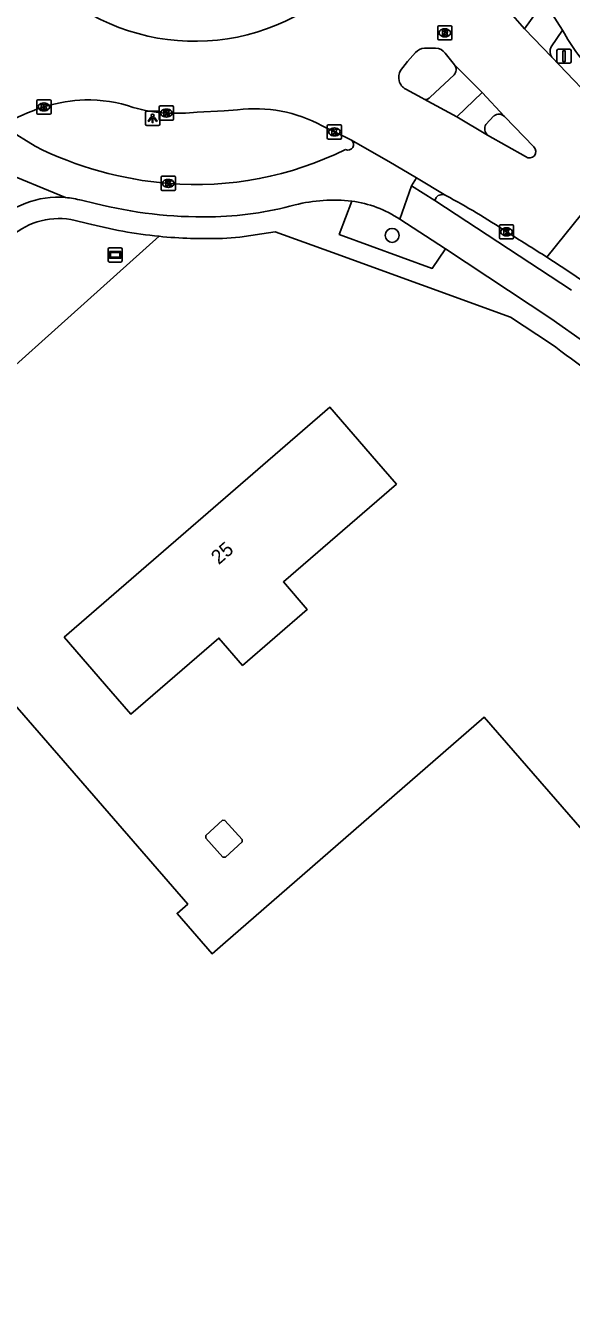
# Model space of a CAD drawing. Extents: x 156141 to 158132, y 385651 to 388399.
# Drawn here: x 156663.7 to 156702, y 386916.4 to 387006.5 of the extents above; entities that cross this region are included whole.
import ezdxf

# ---------------------------------------------------------------- set-up
doc = ezdxf.new("R2010")
doc.units = 0
for name, color, linetype in [('IMGEO_Boom', 7, 'Continuous'), ('IMGEO_Fietspad_gesloten', 7, 'Continuous'), ('IMGEO_Groenvoorziening', 7, 'Continuous'), ('IMGEO_Hek', 7, 'Continuous'), ('IMGEO_Kolk', 7, 'Continuous'), ('IMGEO_Lage_trafo', 7, 'Continuous'), ('IMGEO_Lichtpunt', 7, 'Continuous'), ('IMGEO_Pand', 7, 'Continuous'), ('IMGEO_Pand_nummerreeks', 7, 'Continuous'), ('IMGEO_Rijbaan_lokaal_gesloten', 7, 'Continuous'), ('IMGEO_Rioolput', 7, 'Continuous'), ('IMGEO_Verkeersbordpaal', 7, 'Continuous'), ('IMGEO_Verklikker', 7, 'Continuous'), ('IMGEO_Voetpad_gesloten', 7, 'Continuous'), ('IMGEO_Voetpad_open', 7, 'Continuous')]:
    doc.layers.add(name, color=color, linetype=linetype)

msp = doc.modelspace()

# ---------------------------------------------------------------- linework, layer by layer
at = {"layer": 'IMGEO_Boom'}
msp.add_circle((156689.433, 386991.752), 0.489, dxfattribs=at)
at = {"layer": 'IMGEO_Fietspad_gesloten'}
for points in [[(156698.711, 387006.225), (156700.096, 387008.143), (156701.387, 387006.132)], [(156693.775, 387002.996), (156692.105, 387001.447)], [(156695.751, 387001.772), (156693.974, 387000.053)], [(156664.391, 386998), (156662.509, 386999.178)], [(156661.84, 386996.318), (156666.533, 386994.404)], [(156689.966, 386992.892), (156690.795, 386995.224)], [(156691.132, 386995.796), (156690.795, 386995.224)], [(156690.795, 386995.224), (156692.417, 386994.202)], [(156668.614, 386993.983), (156667.65, 386994.209)], [(156702.016, 386987.906), (156692.417, 386994.202)], [(156689.966, 386992.892), (156693.165, 386990.801)], [(156703.023, 386984.189), (156700.556, 386985.925), (156693.165, 386990.801)]]:
    msp.add_lwpolyline(points, dxfattribs=at)
for centre, radius, start, end in [((156713.634, 387012.787), 13.938, 208.5177, 224.98093), ((156693.328, 387003.377), 0.587, 319.52372, 34.19696), ((156691.781, 387001.685), 0.402, 256.11781, 323.67305), ((156675.767, 387020.752), 25.438, 243.4358, 265.41669), ((156686.341, 386998.114), 0.383, 241.1208, 58.64655), ((156675.698, 387018.728), 23.415, 265.18946, 296.52958), ((156665.996, 386988.061), 6.366, 85.16238, 136.3351), ((156666.026, 386988.205), 6.22, 74.86733, 85.32747), ((156676.28, 387024.756), 31.713, 256.01146, 270.71731), ((156676.29, 387017.188), 24.146, 270.9173, 285.22162), ((156685.357, 386983.114), 11.114, 83.58227, 104.20108), ((156685.487, 386986.096), 8.139, 56.6108, 82.14663)]:
    msp.add_arc(centre, radius, start, end, dxfattribs=at)
at = {"layer": 'IMGEO_Groenvoorziening'}
msp.add_lwpolyline([(156673.084, 386991.685), (156655.481, 386975.893)], dxfattribs=at)
at = {"layer": 'IMGEO_Hek'}
msp.add_lwpolyline([(156655.481, 386975.893), (156673.084, 386991.685)], dxfattribs=at)
at = {"layer": 'IMGEO_Kolk'}
for p, q in [((156664.51, 387000.33), (156664.51, 387001.182)), ((156664.585, 387001.256), (156665.437, 387001.256)), ((156664.998, 387001.036), (156665.023, 387001.036)), ((156665.511, 387001.182), (156665.511, 387000.33)), ((156673.101, 386999.898), (156673.101, 387000.75)), ((156673.176, 387000.824), (156674.028, 387000.824)), ((156673.589, 387000.604), (156673.614, 387000.604)), ((156674.102, 387000.75), (156674.102, 386999.898)), ((156665.437, 387000.256), (156664.585, 387000.256)), ((156665.021, 387000.476), (156664.996, 387000.476)), ((156674.028, 386999.824), (156673.176, 386999.824)), ((156673.612, 387000.044), (156673.587, 387000.044)), ((156684.886, 386998.58), (156684.886, 386999.432)), ((156684.961, 386999.506), (156685.813, 386999.506)), ((156685.374, 386999.286), (156685.399, 386999.286)), ((156685.887, 386999.432), (156685.887, 386998.58)), ((156685.813, 386998.506), (156684.961, 386998.506)), ((156685.397, 386998.726), (156685.372, 386998.726)), ((156673.233, 386994.971), (156673.233, 386995.823)), ((156673.308, 386995.897), (156674.16, 386995.897)), ((156673.721, 386995.677), (156673.746, 386995.677)), ((156674.234, 386995.823), (156674.234, 386994.971)), ((156674.16, 386994.897), (156673.308, 386994.897)), ((156673.744, 386995.117), (156673.719, 386995.117)), ((156697.026, 386992.5), (156697.878, 386992.5)), ((156696.951, 386991.574), (156696.951, 386992.426)), ((156697.462, 386991.72), (156697.437, 386991.72)), ((156697.439, 386992.28), (156697.464, 386992.28)), ((156697.952, 386992.426), (156697.952, 386991.574)), ((156697.878, 386991.5), (156697.026, 386991.5))]:
    msp.add_line(p, q, dxfattribs=at)
for points in [[(156664.51, 387000.33), (156664.51, 387001.182)], [(156664.585, 387001.256), (156665.437, 387001.256)], [(156664.831, 387000.956), (156664.954, 387000.956), (156664.954, 387000.805), (156665.084, 387000.956), (156665.248, 387000.956), (156665.102, 387000.805), (156665.255, 387000.556), (156665.103, 387000.556), (156665.018, 387000.72), (156664.954, 387000.653), (156664.954, 387000.556), (156664.831, 387000.556), (156664.831, 387000.956)], [(156665.511, 387001.182), (156665.511, 387000.33)], [(156673.101, 386999.898), (156673.101, 387000.75)], [(156673.176, 387000.824), (156674.028, 387000.824)], [(156674.102, 387000.75), (156674.102, 386999.898)], [(156665.437, 387000.256), (156664.585, 387000.256)], [(156674.028, 386999.824), (156673.176, 386999.824)], [(156673.422, 387000.524), (156673.545, 387000.524), (156673.545, 387000.373), (156673.675, 387000.524), (156673.839, 387000.524), (156673.693, 387000.373), (156673.846, 387000.124), (156673.694, 387000.124), (156673.609, 387000.288), (156673.545, 387000.221), (156673.545, 387000.124), (156673.422, 387000.124), (156673.422, 387000.524)], [(156684.886, 386998.58), (156684.886, 386999.432)], [(156684.961, 386999.506), (156685.813, 386999.506)], [(156685.207, 386999.206), (156685.33, 386999.206), (156685.33, 386999.055), (156685.46, 386999.206), (156685.624, 386999.206), (156685.478, 386999.055), (156685.631, 386998.806), (156685.479, 386998.806), (156685.394, 386998.97), (156685.33, 386998.903), (156685.33, 386998.806), (156685.207, 386998.806), (156685.207, 386999.206)], [(156685.887, 386999.432), (156685.887, 386998.58)], [(156685.813, 386998.506), (156684.961, 386998.506)], [(156673.233, 386994.971), (156673.233, 386995.823)], [(156673.308, 386995.897), (156674.16, 386995.897)], [(156673.554, 386995.597), (156673.677, 386995.597), (156673.677, 386995.446), (156673.807, 386995.597), (156673.971, 386995.597), (156673.825, 386995.446), (156673.978, 386995.197), (156673.826, 386995.197), (156673.741, 386995.361), (156673.677, 386995.294), (156673.677, 386995.197), (156673.554, 386995.197), (156673.554, 386995.597)], [(156674.234, 386995.823), (156674.234, 386994.971)], [(156674.16, 386994.897), (156673.308, 386994.897)], [(156697.026, 386992.5), (156697.878, 386992.5)], [(156696.951, 386991.574), (156696.951, 386992.426)], [(156697.272, 386992.2), (156697.395, 386992.2), (156697.395, 386992.049), (156697.525, 386992.2), (156697.689, 386992.2), (156697.543, 386992.049), (156697.696, 386991.8), (156697.544, 386991.8), (156697.459, 386991.964), (156697.395, 386991.897), (156697.395, 386991.8), (156697.272, 386991.8), (156697.272, 386992.2)], [(156697.952, 386992.426), (156697.952, 386991.574)], [(156697.878, 386991.5), (156697.026, 386991.5)]]:
    msp.add_lwpolyline(points, dxfattribs=at)
for centre, start, end in [((156664.587, 387001.18), 91.55205, 178.44795), ((156664.587, 387001.18), 91.55205, 178.44795), ((156665.435, 387001.18), 1.55205, 88.44795), ((156665.435, 387001.18), 1.55205, 88.44795), ((156673.178, 387000.748), 91.55205, 178.44795), ((156673.178, 387000.748), 91.55205, 178.44795), ((156674.026, 387000.748), 1.55205, 88.44795), ((156674.026, 387000.748), 1.55205, 88.44795), ((156664.587, 387000.332), 181.55205, 268.44795), ((156664.587, 387000.332), 181.55205, 268.44795), ((156665.435, 387000.332), 271.55205, 358.44795), ((156665.435, 387000.332), 271.55205, 358.44795), ((156673.178, 386999.9), 181.55205, 268.44795), ((156673.178, 386999.9), 181.55205, 268.44795), ((156674.026, 386999.9), 271.55205, 358.44795), ((156674.026, 386999.9), 271.55205, 358.44795), ((156684.963, 386999.43), 91.55205, 178.44795), ((156684.963, 386999.43), 91.55205, 178.44795), ((156685.811, 386999.43), 1.55205, 88.44795), ((156685.811, 386999.43), 1.55205, 88.44795), ((156684.963, 386998.582), 181.55205, 268.44795), ((156684.963, 386998.582), 181.55205, 268.44795), ((156685.811, 386998.582), 271.55205, 358.44795), ((156685.811, 386998.582), 271.55205, 358.44795), ((156673.31, 386995.821), 91.55205, 178.44795), ((156673.31, 386995.821), 91.55205, 178.44795), ((156674.158, 386995.821), 1.55205, 88.44795), ((156674.158, 386995.821), 1.55205, 88.44795), ((156673.31, 386994.973), 181.55205, 268.44795), ((156673.31, 386994.973), 181.55205, 268.44795), ((156674.158, 386994.973), 271.55205, 358.44795), ((156674.158, 386994.973), 271.55205, 358.44795), ((156697.028, 386992.424), 91.55205, 178.44795), ((156697.028, 386992.424), 91.55205, 178.44795), ((156697.876, 386992.424), 1.55205, 88.44795), ((156697.876, 386992.424), 1.55205, 88.44795), ((156697.028, 386991.576), 181.55205, 268.44795), ((156697.028, 386991.576), 181.55205, 268.44795), ((156697.876, 386991.576), 271.55205, 358.44795), ((156697.876, 386991.576), 271.55205, 358.44795)]:
    msp.add_arc(centre, 0.0765, start, end, dxfattribs=at)
for centre, major_axis, ratio, start_param, end_param in [((156664.997, 387000.756), (-0.387, 0.002), 0.722429, 4.712389, 7.853982), ((156665.022, 387000.756), (-0.39, 0.002), 0.717154, 1.570796, 4.712389), ((156673.588, 387000.324), (-0.387, 0.002), 0.722429, 4.712389, 7.853982), ((156673.613, 387000.324), (-0.39, 0.002), 0.717154, 1.570796, 4.712389), ((156685.373, 386999.006), (-0.387, 0.002), 0.722429, 4.712389, 7.853982), ((156685.398, 386999.006), (-0.39, 0.002), 0.717154, 1.570796, 4.712389), ((156673.72, 386995.397), (-0.387, 0.002), 0.722429, 4.712389, 7.853982), ((156673.745, 386995.397), (-0.39, 0.002), 0.717154, 1.570796, 4.712389), ((156697.438, 386992), (-0.387, 0.002), 0.722429, 4.712389, 7.853982), ((156697.463, 386992), (-0.39, 0.002), 0.717154, 1.570796, 4.712389)]:
    msp.add_ellipse(centre, major_axis=major_axis, ratio=ratio, start_param=start_param, end_param=end_param, dxfattribs=at)
at = {"layer": 'IMGEO_Lage_trafo'}
msp.add_lwpolyline([(156676.361, 386949.497), (156676.371, 386949.672), (156677.539, 386950.742), (156677.709, 386950.734), (156678.912, 386949.403), (156678.921, 386949.226), (156677.749, 386948.16), (156677.562, 386948.171), (156676.361, 386949.497)], dxfattribs=at)
at = {"layer": 'IMGEO_Lichtpunt'}
for p, q in [((156672.139, 387000.363), (156672.139, 386999.556)), ((156672.139, 387000.363), (156672.139, 386999.556)), ((156673.041, 387000.458), (156672.233, 387000.458)), ((156673.041, 387000.458), (156672.233, 387000.458)), ((156673.135, 386999.556), (156673.135, 387000.363)), ((156673.135, 386999.556), (156673.135, 387000.363)), ((156672.233, 386999.462), (156673.041, 386999.462)), ((156672.233, 386999.462), (156673.041, 386999.462))]:
    msp.add_line(p, q, dxfattribs=at)
for points in [[(156672.513, 387000.027), (156672.552, 386999.999), (156672.364, 386999.737), (156672.326, 386999.764), (156672.513, 387000.027)], [(156672.615, 386999.979), (156672.662, 386999.979), (156672.662, 386999.657), (156672.615, 386999.657), (156672.615, 386999.979)], [(156672.725, 386999.999), (156672.763, 387000.026), (156672.95, 386999.764), (156672.911, 386999.736), (156672.725, 386999.999)]]:
    msp.add_lwpolyline(points, dxfattribs=at)
msp.add_circle((156672.638, 387000.161), 0.0994, dxfattribs=at)
for centre, start, end in [((156672.233, 387000.363), 90, 180), ((156672.233, 387000.363), 90, 180), ((156673.041, 387000.363), 0, 90), ((156673.041, 387000.363), 0, 90), ((156672.233, 386999.556), 180, 270), ((156672.233, 386999.556), 180, 270), ((156673.041, 386999.556), 270, 0), ((156673.041, 386999.556), 270, 360)]:
    msp.add_arc(centre, 0.0946, start, end, dxfattribs=at)
at = {"layer": 'IMGEO_Pand'}
for points in [[(156666.435, 386963.585), (156685.066, 386979.707), (156688.338, 386975.926), (156689.732, 386974.316), (156681.806, 386967.458), (156683.477, 386965.527), (156678.942, 386961.603), (156677.285, 386963.518), (156671.114, 386958.178), (156669.706, 386959.805), (156666.435, 386963.585)], [(156632.813, 386922.979), (156634.616, 386924.548), (156624.471, 386936.156), (156653.216, 386961.202), (156653.899, 386960.418), (156657.074, 386963.181), (156656.396, 386963.957), (156657.592, 386965.002), (156675.1, 386944.876), (156674.346, 386944.22), (156676.807, 386941.391), (156677.562, 386942.047), (156695.881, 386957.981), (156709.331, 386942.518), (156708.055, 386941.409), (156711.049, 386937.974), (156712.323, 386939.084), (156722.503, 386927.388), (156699.852, 386907.726), (156709.71, 386896.409), (156679.137, 386869.744), (156632.813, 386922.979)]]:
    msp.add_lwpolyline(points, dxfattribs=at)
at = {"layer": 'IMGEO_Rijbaan_lokaal_gesloten'}
for points in [[(156697.053, 387008.162), (156697.416, 387007.737), (156698.711, 387006.225)], [(156700.643, 387004.256), (156698.711, 387006.225)], [(156690.024, 387003.314), (156690.513, 387003.945), (156691.076, 387004.581)], [(156691.699, 387004.871), (156692.479, 387004.875)], [(156693.153, 387004.516), (156693.814, 387003.707)], [(156706.491, 386997.928), (156704.25, 387000.459), (156700.643, 387004.256)], [(156693.814, 387003.707), (156695.751, 387001.772)], [(156691.685, 387001.295), (156691.506, 387001.392), (156690.387, 387002.002)], [(156695.751, 387001.772), (156697.301, 387000.092)], [(156675.762, 387000.384), (156677.652, 387000.475), (156678.6, 387000.563)], [(156693.974, 387000.053), (156691.685, 387001.295)], [(156696.126, 386998.785), (156693.974, 387000.053)], [(156697.301, 387000.092), (156699.359, 386997.959)], [(156684.526, 386999.439), (156685.387, 386999.006), (156686.54, 386998.441)], [(156698.793, 386997.276), (156696.126, 386998.785)], [(156686.54, 386998.441), (156689.201, 386996.934), (156691.132, 386995.796)], [(156700.285, 386990.228), (156706.491, 386997.928)], [(156693.198, 386994.55), (156691.132, 386995.796)], [(156700.285, 386990.228), (156701.754, 386989.26)]]:
    msp.add_lwpolyline(points, dxfattribs=at)
for centre, radius, start, end in [((156675.597, 387020.358), 15.001, 133.93925, 309.15005), ((156691.751, 387003.946), 0.926, 93.19203, 136.73094), ((156692.481, 387004.067), 0.808, 33.75037, 90.16645), ((156690.828, 387002.83), 0.938, 148.96179, 241.96928), ((156668.487, 386989.344), 11.93, 92.94203, 119.43248), ((156668.04, 386991.235), 10.024, 71.13665, 90.94402), ((156674.212, 387010.872), 10.566, 253.89604, 266.69129), ((156679.781, 386990.608), 10.025, 61.75242, 96.76785), ((156674.286, 387014.608), 14.3, 267.25824, 275.92404), ((156699.073, 386997.62), 0.444, 230.8475, 49.85562), ((156669.268, 386949.806), 50.741, 56.25869, 61.86134), ((157395.376, 388104.661), 1313.435, 237.90174, 238.047508), ((156608.464, 386851.084), 166.72, 52.03516, 55.97478)]:
    msp.add_arc(centre, radius, start, end, dxfattribs=at)
at = {"layer": 'IMGEO_Rioolput'}
for p, q in [((156692.629, 387005.525), (156692.629, 387006.377)), ((156692.704, 387006.451), (156693.556, 387006.451)), ((156693.117, 387006.231), (156693.142, 387006.231)), ((156693.63, 387006.377), (156693.63, 387005.525)), ((156693.556, 387005.451), (156692.704, 387005.451)), ((156693.14, 387005.671), (156693.115, 387005.671))]:
    msp.add_line(p, q, dxfattribs=at)
for points in [[(156692.629, 387005.525), (156692.629, 387006.377)], [(156692.704, 387006.451), (156693.556, 387006.451)], [(156693.218, 387006.149), (156692.966, 387006.151), (156692.966, 387005.751)], [(156693.144, 387006.07), (156693.09, 387006.07), (156693.09, 387005.989)], [(156693.09, 387005.989), (156693.142, 387005.989)], [(156693.63, 387006.377), (156693.63, 387005.525)], [(156693.556, 387005.451), (156692.704, 387005.451)], [(156692.966, 387005.751), (156693.09, 387005.751), (156693.09, 387005.913), (156693.101, 387005.913)], [(156693.148, 387005.884), (156693.219, 387005.751), (156693.359, 387005.751), (156693.294, 387005.877)]]:
    msp.add_lwpolyline(points, dxfattribs=at)
for centre, radius, start, end in [((156692.706, 387006.375), 0.0765, 91.55205, 178.44795), ((156692.706, 387006.375), 0.0765, 91.55205, 178.44795), ((156693.126, 387006.178), 0.19, 274.7715, 282.96867), ((156693.15, 387005.974), 0.0964, 77.00612, 93.18647), ((156693.164, 387006.031), 0.0378, 276.66336, 79.67722), ((156693.217, 387006.039), 0.109, 350.36119, 89.41601), ((156693.215, 387006.039), 0.112, 277.58423, 350.98172), ((156693.554, 387006.375), 0.0765, 1.55205, 88.44795), ((156693.554, 387006.375), 0.0765, 1.55205, 88.44795), ((156692.706, 387005.527), 0.0765, 181.55205, 268.44795), ((156692.706, 387005.527), 0.0765, 181.55205, 268.44795), ((156693.1, 387005.86), 0.0533, 26.02933, 88.69889), ((156693.199, 387005.824), 0.108, 29.51342, 73.79051), ((156693.554, 387005.527), 0.0765, 271.55205, 358.44795), ((156693.554, 387005.527), 0.0765, 271.55205, 358.44795)]:
    msp.add_arc(centre, radius, start, end, dxfattribs=at)
for centre, major_axis, ratio, start_param, end_param in [((156693.116, 387005.951), (-0.387, 0.002), 0.722429, 4.712389, 7.853982), ((156693.141, 387005.951), (-0.39, 0.002), 0.717154, 1.570796, 4.712389)]:
    msp.add_ellipse(centre, major_axis=major_axis, ratio=ratio, start_param=start_param, end_param=end_param, dxfattribs=at)
at = {"layer": 'IMGEO_Verkeersbordpaal'}
for p, q in [((156700.99, 387003.914), (156700.99, 387004.714)), ((156700.99, 387004.714), (156700.99, 387003.914)), ((156701.09, 387004.814), (156701.88, 387004.814)), ((156701.88, 387004.814), (156701.09, 387004.814)), ((156701.98, 387004.714), (156701.98, 387003.914)), ((156701.98, 387003.914), (156701.98, 387004.714)), ((156701.88, 387003.814), (156701.09, 387003.814)), ((156701.09, 387003.814), (156701.88, 387003.814))]:
    msp.add_line(p, q, dxfattribs=at)
msp.add_lwpolyline([(156701.41, 387004.689), (156701.56, 387004.689), (156701.56, 387003.939), (156701.41, 387003.939), (156701.41, 387004.689)], dxfattribs=at)
for centre, start, end in [((156701.09, 387004.714), 90, 180), ((156701.09, 387004.714), 90, 180), ((156701.88, 387004.714), 0, 90), ((156701.88, 387004.714), 360, 90), ((156701.09, 387003.914), 180, 270), ((156701.09, 387003.914), 180, 270), ((156701.88, 387003.914), 270, 0), ((156701.88, 387003.914), 270, 0)]:
    msp.add_arc(centre, 0.1, start, end, dxfattribs=at)
at = {"layer": 'IMGEO_Verklikker'}
for p, q in [((156669.512, 386989.984), (156669.512, 386990.784)), ((156669.512, 386990.784), (156669.512, 386989.984)), ((156669.612, 386990.884), (156670.402, 386990.884)), ((156670.402, 386990.884), (156669.612, 386990.884)), ((156670.502, 386990.784), (156670.502, 386989.984)), ((156670.502, 386989.984), (156670.502, 386990.784)), ((156670.402, 386989.884), (156669.612, 386989.884)), ((156669.612, 386989.884), (156670.402, 386989.884))]:
    msp.add_line(p, q, dxfattribs=at)
for points in [[(156669.613, 386990.616), (156670.401, 386990.616), (156670.401, 386990.152), (156669.613, 386990.152), (156669.613, 386990.616)], [(156669.678, 386990.551), (156669.678, 386990.217), (156670.336, 386990.217), (156670.336, 386990.551), (156669.678, 386990.551)]]:
    msp.add_lwpolyline(points, dxfattribs=at)
for centre, start, end in [((156669.612, 386990.784), 90, 180), ((156669.612, 386990.784), 90, 180), ((156670.402, 386990.784), 0, 90), ((156670.402, 386990.784), 360, 90), ((156669.612, 386989.984), 180, 270), ((156669.612, 386989.984), 180, 270), ((156670.402, 386989.984), 270, 0), ((156670.402, 386989.984), 270, 0)]:
    msp.add_arc(centre, 0.1, start, end, dxfattribs=at)
at = {"layer": 'IMGEO_Voetpad_gesloten'}
msp.add_lwpolyline([(156695.997, 386999.535), (156696.576, 387000.122)], dxfattribs=at)
for centre, radius, start, end in [((156696.923, 386999.729), 0.524, 43.85066, 131.41032), ((156696.56, 386999.246), 0.633, 152.79102, 226.72775)]:
    msp.add_arc(centre, radius, start, end, dxfattribs=at)
at = {"layer": 'IMGEO_Voetpad_open'}
for points in [[(156700.593, 387004.966), (156701.387, 387006.132)], [(156692.417, 386994.202), (156692.525, 386994.411)], [(156693.165, 386990.801), (156692.243, 386989.437), (156685.726, 386991.819), (156686.599, 386994.159)], [(156667.2, 386992.801), (156668.058, 386992.593)], [(156677.529, 386991.543), (156678.752, 386991.632), (156680.289, 386991.852), (156681.241, 386992.002), (156685.251, 386990.546), (156697.738, 386986.014), (156700.528, 386984.181)]]:
    msp.add_lwpolyline(points, dxfattribs=at)
for centre, radius, start, end in [((156701.143, 387004.648), 0.636, 149.98204, 218.07448), ((156692.945, 386994.076), 0.538, 61.94547, 141.39386), ((156666.057, 386987.878), 5.054, 76.92813, 131.24676), ((156676.38, 387024.293), 32.774, 255.29053, 264.22821), ((156676.343, 387024.072), 32.55, 264.25312, 272.08738), ((156650.012, 386913.922), 86.534, 49.39568, 54.28376)]:
    msp.add_arc(centre, radius, start, end, dxfattribs=at)

# ---------------------------------------------------------------- texts
at = {"layer": 'IMGEO_Pand_nummerreeks'}
msp.add_text('25', height=1, rotation=40.87068, dxfattribs=at).set_placement((156677.274, 386968.627))

doc.saveas('drawing.dxf')
